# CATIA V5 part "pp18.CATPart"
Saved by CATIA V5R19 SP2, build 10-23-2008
Part number: pp18
Publications: "Line.1", "Line.2", "Line.3", "Plane.1", "Plane.2", "Line.4", "Vertex"
Bounding box of the stored display mesh (mm): x -10 to 10, y -421.951 to 0, z -51.894 to 0
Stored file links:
  C:\Users\Welcome\Documents\thinkm2\pp18.CATPart
  C:\Users\Welcome\Documents\thinkm2\Brasmeca.CATProduct
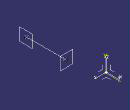
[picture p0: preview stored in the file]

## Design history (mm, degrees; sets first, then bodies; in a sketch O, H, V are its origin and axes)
AxisSystem1: origin (0, 0, 0), X (1, 0, 0), Y (0, 1, 0), Z (0, 0, 1)
Set1
  Point1: linked copy from another document
  Point2: linked copy from another document
Body1 (main body)
  Line1: type PtPt, FirstPoint Point1, SecondPoint Point2
  Line2: type PtDir, RefPoint Point1, Direction edge [XY plane of AxisSystem1 | ZX plane of AxisSystem1], Start 0, End 10
  Line3: type PtDir, RefPoint Point2, Direction edge [XY plane of AxisSystem1 | ZX plane of AxisSystem1], Start 0, End -10
  Plane1: type Normal, Curve Line2
  Line4: type PtDir, RefPoint Point2, Direction edge [YZ plane of AxisSystem1 | XY plane of AxisSystem1], Start 0, End 10
  Plane2: type Normal, Curve Line4, RefPoint vertex of Line4
  Sketch1 on Plane1, origin (5, 0, 0), H (0, 1, 0), V (0, 0, 1)
    circle A1 centre (-420.1554, -50.0986) radius 1.7952
    radius A1 = 1.7952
